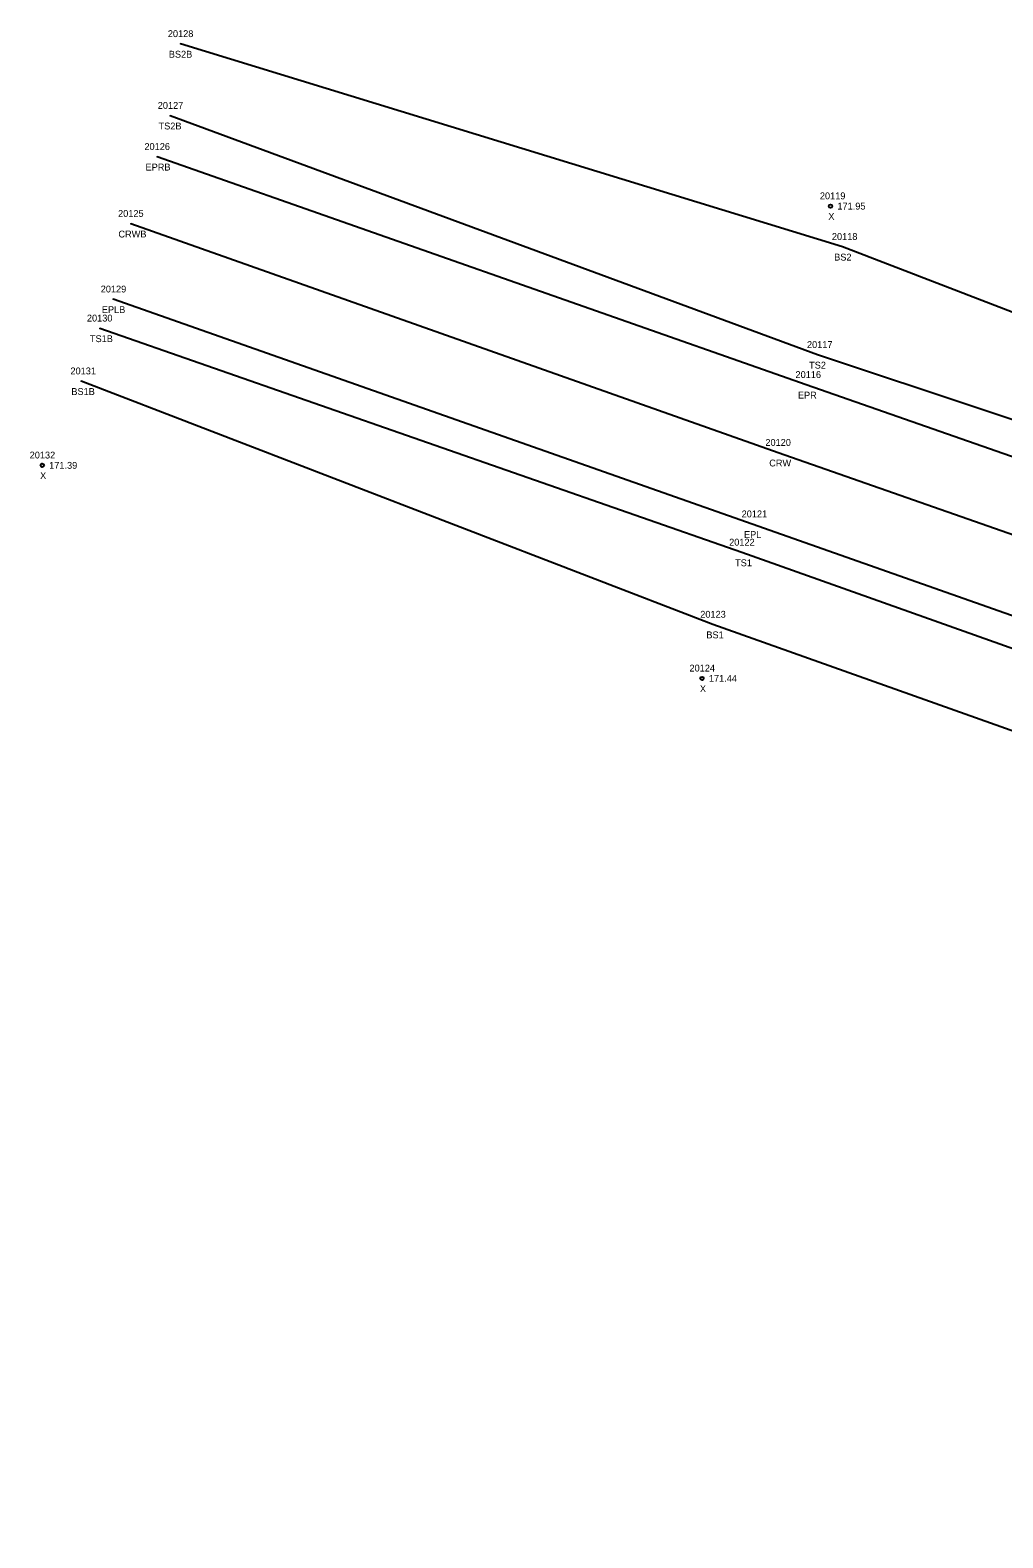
# Model space of a CAD drawing. Extents: x 2054705 to 2055845, y 756616 to 757058.
# Drawn here: x 2054705.4 to 2054847.2, y 756838.4 to 757058.1 of the extents above; entities that cross this region are included whole.
import ezdxf

# ---------------------------------------------------------------- set-up
doc = ezdxf.new("R2010")
doc.units = 0
for name, color, linetype in [('RD_DTM_BkLn1', 7, 'Continuous'), ('RD_DTM_BkLn2', 7, 'Continuous'), ('RD_EX_Road', 7, 'Continuous'), ('RD_EX_Road_txCode', 7, 'Continuous'), ('RD_Sketch8', 7, 'Continuous'), ('RD_SMD_Locator', 7, 'Continuous'), ('RD_SMD_Misc', 7, 'Continuous')]:
    doc.layers.add(name, color=color, linetype=linetype)

msp = doc.modelspace()

# ---------------------------------------------------------------- linework, layer by layer
at = {"layer": 'RD_DTM_BkLn1'}
msp.add_lwpolyline([(2055198.36, 756861.7), (2055105.78, 756894.05), (2055007.93, 756928.48), (2054913.01, 756962.02), (2054814.44, 756996.55), (2054720.09, 757029.92)], dxfattribs=at)
at = {"layer": 'RD_DTM_BkLn2'}
for points in [[(2055211.27, 756885.1), (2055111.97, 756928.98), (2055016.09, 756958.06), (2054925.03, 756987.54), (2054823.8, 757026.56), (2054727.34, 757056.13)], [(2055202.66, 756871.32), (2055205.34, 756878.01), (2055110.35, 756912.5), (2055013.19, 756941.9), (2054919.26, 756977.81), (2054820.17, 757010.81), (2054725.86, 757045.67)], [(2055194.23, 756850.45), (2055191.32, 756843.16), (2055102.38, 756877.36), (2055003.34, 756913.89), (2054907.82, 756946.94), (2054809.11, 756982.01), (2054715.58, 757014.67)], [(2055191.63, 756838.39), (2055097.99, 756868.2), (2055000.1, 756903.36), (2054903.44, 756936.48), (2054804.9, 756971.5), (2054712.86, 757006.97)]]:
    msp.add_lwpolyline(points, dxfattribs=at)
at = {"layer": 'RD_EX_Road'}
for points in [[(2055198.36, 756861.7), (2055202.66, 756871.32), (2055108.14, 756904.32), (2055012.29, 756937.9), (2054917, 756972.03), (2054818.52, 757006.44), (2054723.95, 757039.68)], [(2055198.36, 756861.7), (2055194.23, 756850.45), (2055102.54, 756883.31), (2055004.69, 756917.96), (2054909.06, 756951.44), (2054810.65, 756986.13), (2054717.55, 757018.91)]]:
    msp.add_lwpolyline(points, dxfattribs=at)
at = {"layer": 'RD_SMD_Locator'}
for centre, radius in [((2054727.34, 757056.13), 0.001), ((2054725.86, 757045.67), 0.001), ((2054723.95, 757039.68), 0.001), ((2054822.05, 757032.49), 0.25), ((2054720.09, 757029.92), 0.001), ((2054823.8, 757026.56), 0.001), ((2054717.55, 757018.91), 0.001), ((2054715.58, 757014.67), 0.001), ((2054820.17, 757010.81), 0.001), ((2054712.86, 757006.97), 0.001), ((2054818.52, 757006.44), 0.001), ((2054814.44, 756996.55), 0.001), ((2054707.21, 756994.71), 0.25), ((2054810.65, 756986.13), 0.001), ((2054809.11, 756982.01), 0.001), ((2054804.9, 756971.5), 0.001), ((2054803.33, 756963.66), 0.25)]:
    msp.add_circle(centre, radius, dxfattribs=at)

# ---------------------------------------------------------------- texts
at = {"layer": 'RD_EX_Road_txCode'}
for s, p in [('20126', (2054722.09, 757040.68)), ('EPRB', (2054722.25, 757037.68)), ('20129', (2054715.72, 757019.91)), ('EPLB', (2054715.88, 757016.91)), ('20116', (2054816.95, 757007.44)), ('EPR', (2054817.3, 757004.44)), ('20121', (2054809.1, 756987.13)), ('EPL', (2054809.44, 756984.13))]:
    msp.add_text(s, height=1, dxfattribs=at).set_placement(p)
at = {"layer": 'RD_Sketch8'}
for s, p in [('20119', (2054820.5, 757033.49)), ('X', (2054821.73, 757030.49)), ('171.95', (2054823.05, 757031.99)), ('20132', (2054705.37, 756995.71)), ('X', (2054706.89, 756992.71)), ('171.39', (2054708.21, 756994.21)), ('20124', (2054801.5, 756964.66)), ('171.44', (2054804.33, 756963.16)), ('X', (2054803.02, 756961.66))]:
    msp.add_text(s, height=1, dxfattribs=at).set_placement(p)
at = {"layer": 'RD_SMD_Misc'}
for s, p in [('20128', (2054725.5, 757057.13)), ('BS2B', (2054725.64, 757054.13)), ('20127', (2054724.03, 757046.67)), ('TS2B', (2054724.15, 757043.67)), ('20125', (2054718.25, 757030.92)), ('CRWB', (2054718.3, 757027.92)), ('20118', (2054822.25, 757027.56)), ('BS2', (2054822.58, 757024.56)), ('20130', (2054713.71, 757015.67)), ('TS1B', (2054714.15, 757012.67)), ('20117', (2054818.62, 757011.81)), ('20131', (2054711.31, 757007.97)), ('TS2', (2054818.93, 757008.81)), ('BS1B', (2054711.44, 757004.97)), ('20120', (2054812.56, 756997.55)), ('CRW', (2054813.12, 756994.55)), ('20122', (2054807.28, 756983.01)), ('TS1', (2054808.15, 756980.01)), ('20123', (2054803.07, 756972.5)), ('BS1', (2054803.96, 756969.5))]:
    msp.add_text(s, height=1, dxfattribs=at).set_placement(p)

doc.saveas('drawing.dxf')
